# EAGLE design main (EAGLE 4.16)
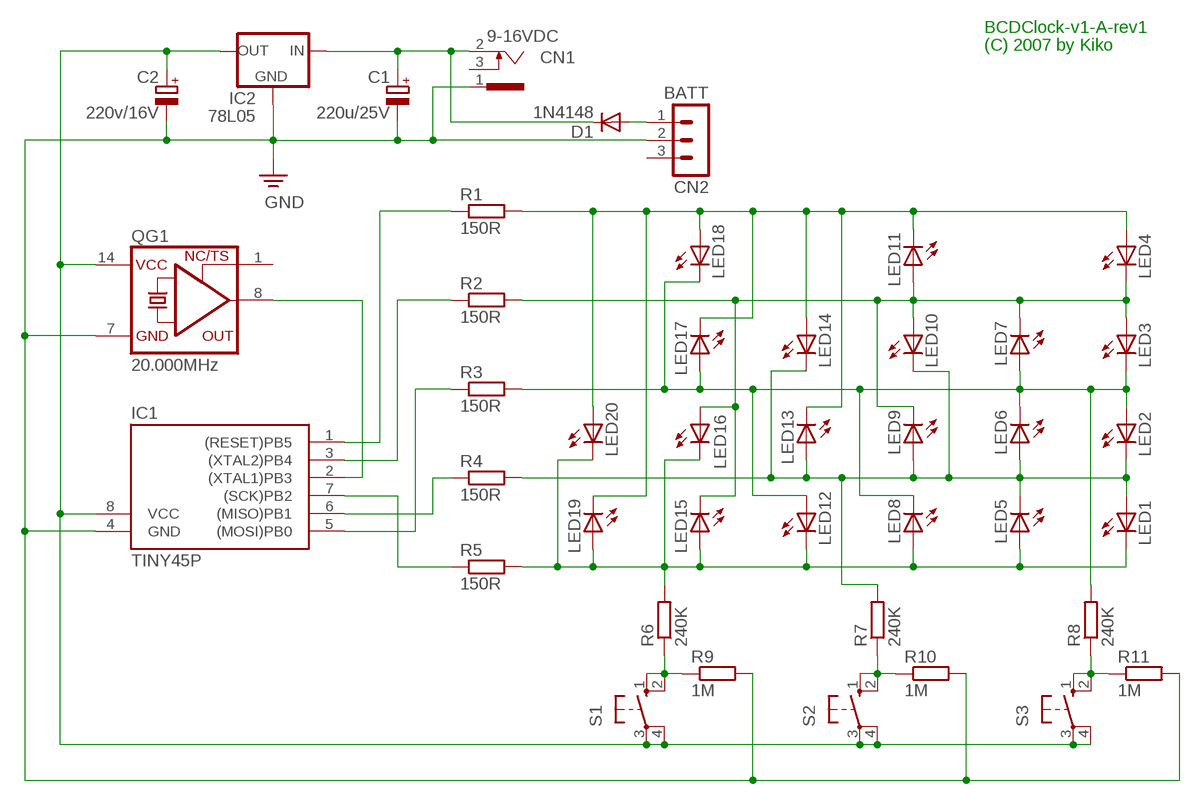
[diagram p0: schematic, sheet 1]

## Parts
C1  220u/25V  CPOL-EUE2.5-6  [E2,5-6]
C2  220v/16V  CPOL-EUE2.5-5  [E2,5-5]
CN1  9-16VDC  SCD-014A  [SCD-014-A]
CN2  BATT  MA03-1  [MA03-1]
D1  1N4148  [DO35-10]
IC1  TINY45P  TINY12P  [DIL08]
IC2  78L05  78LXX  [78LXX]
LED1  LED5MM  [LED5MM]
LED2  LED5MM  [LED5MM]
LED3  LED5MM  [LED5MM]
LED4  LED5MM  [LED5MM]
LED5  LED5MM  [LED5MM]
LED6  LED5MM  [LED5MM]
LED7  LED5MM  [LED5MM]
LED8  LED5MM  [LED5MM]
LED9  LED5MM  [LED5MM]
LED10  LED5MM  [LED5MM]
LED11  LED5MM  [LED5MM]
LED12  LED5MM  [LED5MM]
LED13  LED5MM  [LED5MM]
LED14  LED5MM  [LED5MM]
LED15  LED5MM  [LED5MM]
LED16  LED5MM  [LED5MM]
LED17  LED5MM  [LED5MM]
LED18  LED5MM  [LED5MM]
LED19  LED5MM  [LED5MM]
LED20  LED5MM  [LED5MM]
QG1  20.000MHz  XO-14  [DIL14S]
R1  150R  R-EU_0207/7  [0207/7]
R2  150R  R-EU_0207/7  [0207/7]
R3  150R  R-EU_0207/7  [0207/7]
R4  150R  R-EU_0207/7  [0207/7]
R5  150R  R-EU_0207/7  [0207/7]
R6  240K  R-EU_0207/7  [0207/7]
R7  240K  R-EU_0207/7  [0207/7]
R8  240K  R-EU_0207/7  [0207/7]
R9  1M  R-EU_0207/7  [0207/7]
R10  1M  R-EU_0207/7  [0207/7]
R11  1M  R-EU_0207/7  [0207/7]
S1  40-XX  [B3F-40XX]
S2  40-XX  [B3F-40XX]
S3  40-XX  [B3F-40XX]

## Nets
GND: C1.- C2.- CN1.1 CN2.2 IC1.4(GND) IC2.GND QG1.7(GND) R9.2 R10.2 R11.2
N$1: C1.+ CN1.2 D1.C IC2.IN
N$2: C2.+ IC1.8(VCC) IC2.OUT QG1.14(VCC) S1.3(P) S1.4(P1) S2.3(P) S2.4(P1) S3.3(P) S3.4(P1)
N$3: IC1.2((XTAL1)PB3) QG1.8(OUT)
N$4: IC1.1((RESET)PB5) R1.1
N$5: IC1.3((XTAL2)PB4) R2.1
N$6: IC1.5((MOSI)PB0) R3.1
N$7: IC1.6((MISO)PB1) R4.1
N$8: IC1.7((SCK)PB2) R5.1
N$9: LED4.A LED11.K(C) LED13.K(C) LED14.A LED17.K(C) LED18.A LED19.K(C) LED20.A R1.2
N$10: LED3.A LED4.K(C) LED7.K(C) LED9.K(C) LED10.A LED11.A LED15.K(C) LED16.A R2.2
N$11: LED1.K(C) LED5.A LED8.A LED12.K(C) LED15.A LED16.K(C) LED19.A LED20.K(C) R5.2 R6.2
N$12: LED1.A LED2.K(C) LED5.K(C) LED6.A LED9.A LED10.K(C) LED13.A LED14.K(C) R4.2 R7.2
N$13: LED2.A LED3.K(C) LED6.K(C) LED7.A LED8.K(C) LED12.A LED17.A LED18.K(C) R3.2 R8.2
N$14: CN2.1 D1.A
N$15: R6.1 R9.1 S1.1(S) S1.2(S1)
N$16: R7.1 R10.1 S2.1(S) S2.2(S1)
N$17: R8.1 R11.1 S3.1(S) S3.2(S1)
Unconnected: CN1.3 CN2.3 QG1.1(TS)

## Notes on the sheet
- BCDClock-v1-A-rev1
- (C) 2007 by Kiko

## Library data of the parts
C1 C2 = rcl:CPOL-EU: POLARIZED CAPACITOR, European symbol
CN1 = con-shiua-chyuan:SCD-014A: Power Jack 2.5mm
CN2 = con-lstb:MA03-1: PIN HEADER
D1 = diode:1N4148: DIODE
IC1 = atmel2:TINY12*: MICROCONTROLLER 1 Kbytes FLASH 64 bytes EEPROM
IC2 = v-reg:78LXX: VOLTAGE REGULATOR
LED1-LED20 = led:LED: LED
QG1 = crystal:XO-: CRYSTAL
R1-R11 = rcl:R-EU_: RESISTOR, European symbol
S1-S3 = switch-omron:40-XX: OMRON SWITCH

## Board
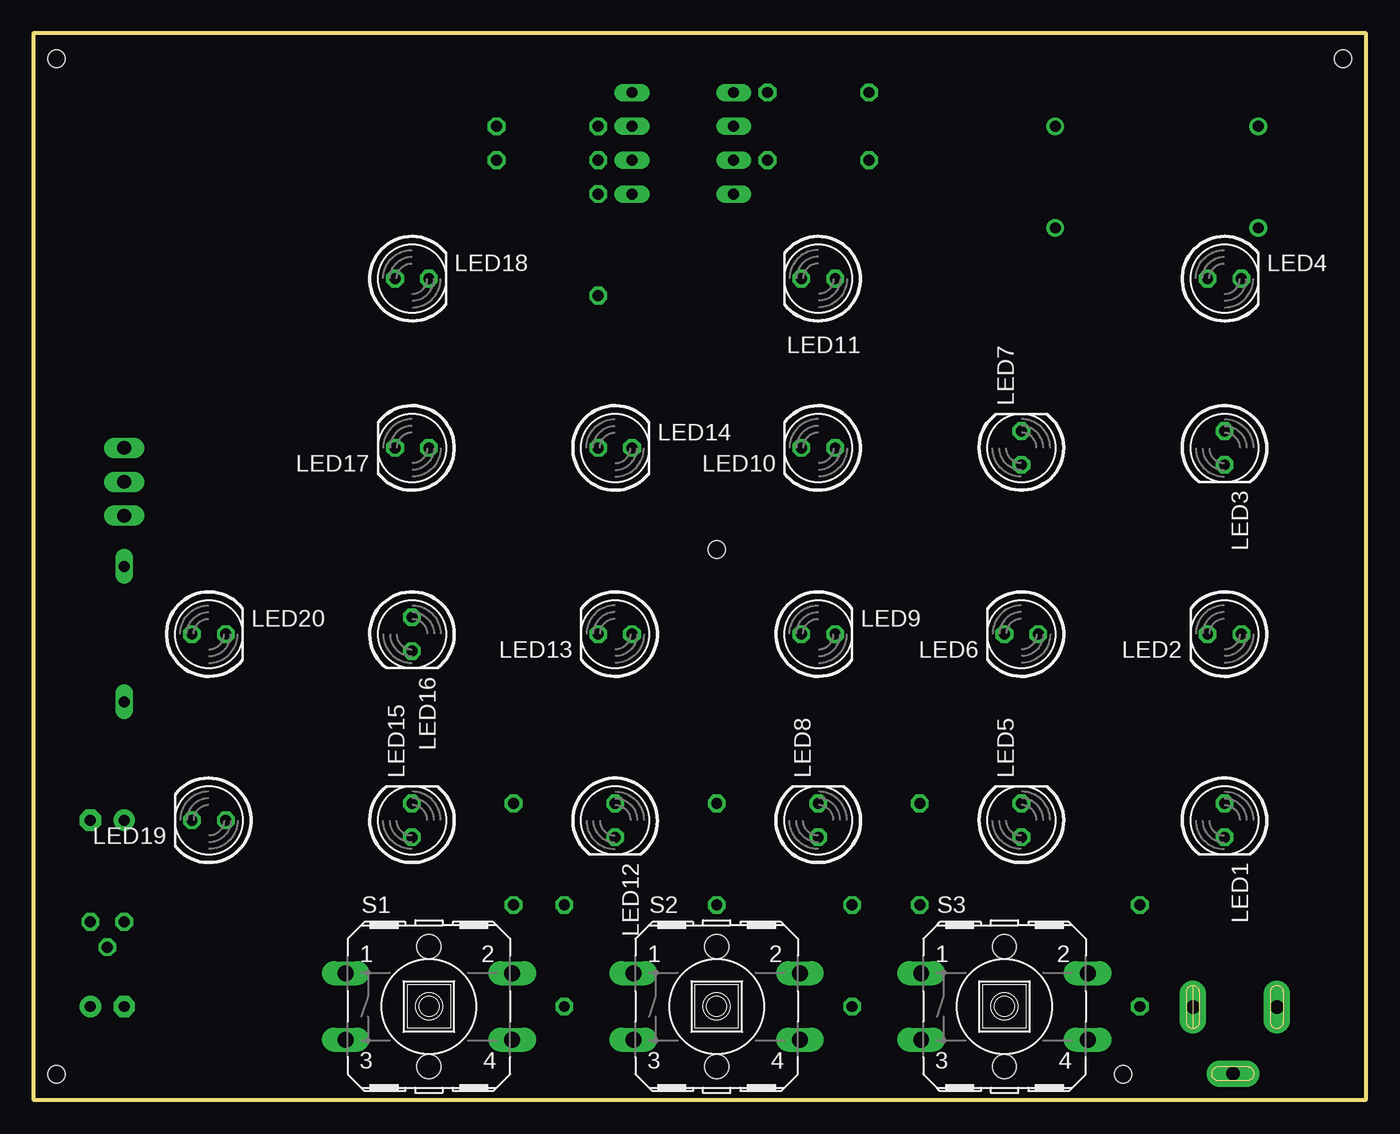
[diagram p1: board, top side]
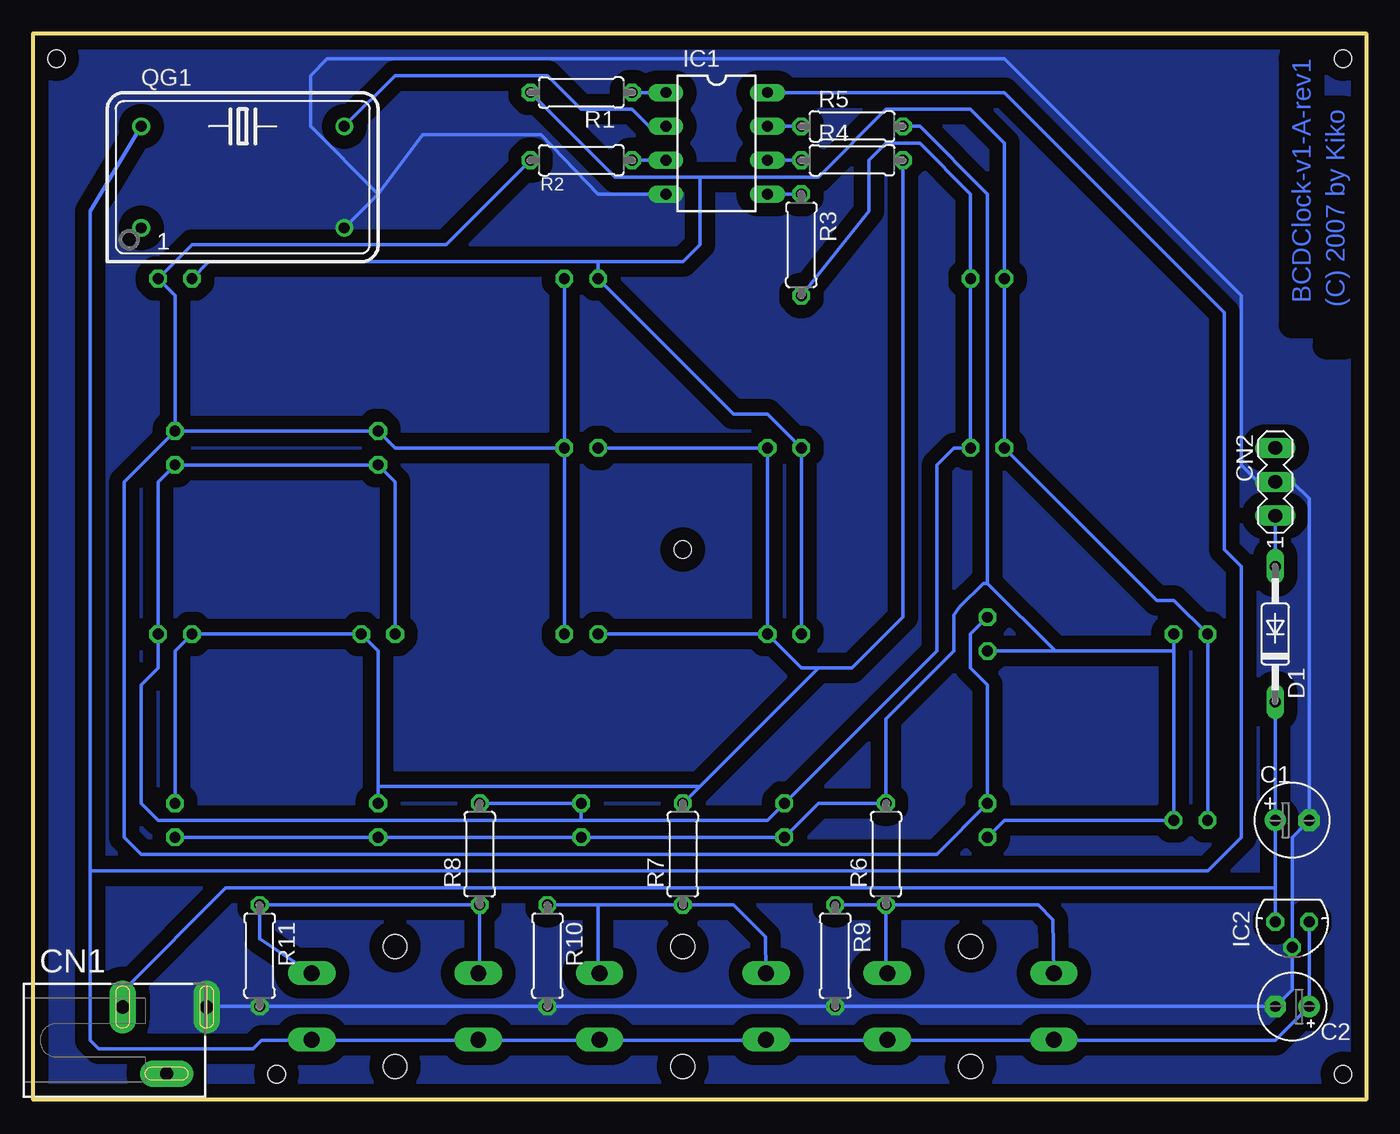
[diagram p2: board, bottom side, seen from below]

Size 100 x 80 mm. Coordinates in mm from the lower left corner, seen from the top.
Outline: 0,0 100,0 100,80 0,80 0,0
Copper layers (1*16): Top 0.035mm / dielectric 1.5mm / Bottom 0.035mm
Design rules "default": minimum track width 10mil, minimum drill 24mil, track to track 8mil, track to pad 8mil, pad to pad 8mil, via to via 8mil, smd to smd 8mil, copper to edge 40mil, drill to drill 8mil, minimum pad ring 10mil, minimum via ring 8mil, stop-mask expansion 4mil, vias tented up to drill 0mil, thermal gap 10mil
Holes 1.3 mm at 1.74,1.9 1.74,78.1 98.26,78.1 81.75,1.9 51.27,41.27

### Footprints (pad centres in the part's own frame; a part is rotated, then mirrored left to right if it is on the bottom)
E2,5-6 = drill 0.813 pad 1.6 round: + -1.27,0 | drill 0.813 pad 1.6 octagon: - 1.27,0
E2,5-5 = drill 0.813 pad 1.6 round: + -1.27,0 | drill 0.813 pad 1.6 octagon: - 1.27,0
SCD-014-A = drill 1 pad 2 long: 1 -2.5,13.8; 2 -2.5,7.5; 3 2.5,10.8
MA03-1 = drill 1.016 long: 1 -2.54,0; 2 0,0; 3 2.54,0
DO35-10 = drill 0.813 long: A 5.08,0; C -5.08,0
DIL08 = drill 0.813 long: 1 -3.81,-3.81; 2 -1.27,-3.81; 3 1.27,-3.81; 4 3.81,-3.81; 5 3.81,3.81; 6 1.27,3.81; 7 -1.27,3.81; 8 -3.81,3.81
78LXX = drill 0.813 octagon: GND 0,1.905; IN 1.27,0; OUT -1.27,0
LED5MM = drill 0.813 octagon: A -1.27,0; K 1.27,0
DIL14S = drill 0.813 round: 1 -7.62,-3.81; 7 7.62,-3.81; 8 7.62,3.81; 14 -7.62,3.81
0207/7 = drill 0.813 octagon: 1 -3.81,0; 2 3.81,0
B3F-40XX = drill 1.194 long: 1 -6.248,2.489; 2 6.248,2.489; 3 -6.248,-2.489; 4 6.248,-2.489 | hole 1.803: 0,-4.496; 0,4.496

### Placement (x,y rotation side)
C1  5.55,20.95 0 bottom
C2  5.55,6.98 180 bottom
CN1  100.8,4.44 270 bottom
CN2  6.82,46.35 90 bottom
D1  6.82,34.92 90 bottom
IC1  48.73,71.75 270 bottom
IC2  5.55,13.33 180 bottom
LED1  89.37,20.95 270 top
LED2  89.37,34.92 180 top
LED3  89.37,48.89 270 top
LED4  89.37,61.59 0 top
LED5  74.13,20.95 90 top
LED6  74.13,34.92 180 top
LED7  74.13,48.89 90 top
LED8  58.89,20.95 90 top
LED9  58.89,34.92 0 top
LED10  58.89,48.89 180 top
LED11  58.89,61.59 180 top
LED12  43.65,20.95 270 top
LED13  43.65,34.92 180 top
LED14  43.65,48.89 0 top
LED15  28.41,20.95 90 top
LED16  28.41,34.92 270 top
LED17  28.41,48.89 180 top
LED18  28.41,61.59 0 top
LED19  13.17,20.95 180 top
LED20  13.17,34.92 0 top
QG1  84.29,69.21 0 bottom
R1  58.89,75.56 180 bottom
R2  58.89,70.48 180 bottom
R3  42.38,64.13 270 bottom
R4  38.57,70.48 0 bottom
R5  38.57,73.02 0 bottom
R6  36.03,18.41 90 bottom
R7  51.27,18.41 90 bottom
R8  66.51,18.41 90 bottom
R9  39.84,10.79 270 bottom
R10  61.43,10.79 270 bottom
R11  83.02,10.79 270 bottom
S1  29.68,6.98 0 top
S2  51.27,6.98 0 top
S3  72.86,6.98 0 top

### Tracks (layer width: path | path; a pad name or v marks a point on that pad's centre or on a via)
GND
  Bottom 0.254: CN1.1 86.83,6.98 R11.2 R10.2 R9.2 C2.- 5.55,8.25 IC2.GND 5.55,19.68 C1.- 4.28,45.08 5.55,46.35 CN2.2 8.09,46.35 9.36,47.62 9.36,60.32 27.14,78.1 77.94,78.1 79.21,76.83 79.21,73.02 74.13,67.94 | 74.13,67.94 QG1.7 | 74.13,67.94 70.8,72.38 61.91,72.38 57.62,67.94 IC1.4
  pour Bottom (isolate 1.016, no thermals): 0.47,79.37 0.47,0.63 99.53,0.63 99.53,79.37
N$1
  Bottom 0.254: 6.82,15.87 C1.+ D1.C | IC2.IN 6.82,15.87 | 6.82,15.87 85.56,15.87 93.18,8.25 CN1.2
N$2
  Bottom 0.254: IC2.OUT C2.+ 6.82,4.44 22.06,4.44 S1.3 24.6,4.44 33.49,4.44 | 33.49,4.44 34.76,4.44 S1.4 37.3,4.44 43.65,4.44 S2.3 | 33.49,4.44 56.35,4.44 S2.4 58.89,4.44 65.24,4.44 S3.3 67.78,4.44 77.94,4.44 S3.4 80.48,4.44 82.86,4.44 83.5,3.8 95.08,3.8 95.72,4.44 95.72,17.14 | QG1.14 95.72,66.67 95.72,17.14 | 95.72,17.14 11.9,17.14 9.36,19.68 9.36,40 10.63,41.27 10.63,59.05 27.14,75.56 IC1.8
N$3
  Bottom 0.254: QG1.8 72.86,76.83 61.43,76.83 58.89,74.29 55.08,74.29 53.81,73.02 IC1.2
N$4
  Bottom 0.254: IC1.1 R1.1
N$5
  Bottom 0.254: IC1.3 R2.1
N$6
  Bottom 0.254: R3.1 IC1.5
N$7
  Bottom 0.254: R4.1 IC1.6
N$8
  Bottom 0.254: R5.1 IC1.7
N$9
  Bottom 0.254: LED19.K LED20.A 14.44,37.46 15.71,37.46 LED17.K LED18.A 27.14,71.75 29.68,74.29 36.03,74.29 41.11,69.21 50,69.21 | LED13.K LED14.A 44.92,51.43 47.46,51.43 LED11.K 57.62,62.86 | R1.2 56.35,69.21 50,69.21 | 50,69.21 50,64.13 51.27,62.86 57.62,62.86 | LED4.A 86.83,62.86 57.62,62.86
N$10
  Bottom 0.254: LED10.A LED9.K | LED10.A 72.86,48.89 LED7.K LED3.A | LED10.A LED11.A | LED16.A 29.68,34.92 29.68,32.38 28.41,31.11 LED15.K 32.22,18.41 91.91,18.41 93.18,19.68 93.18,46.35 LED3.A | LED3.A 89.37,60.32 LED4.K 88.1,64.13 69.05,64.13 R2.2
N$11
  Bottom 0.254: LED1.K LED5.A LED8.A LED12.K 41.11,22.22 R6.2 36.03,28.57 30.95,33.65 30.95,36.35 30.47,36.98 28.73,38.73 28.41,38.73 | 14.44,33.65 LED20.K | 14.44,33.65 LED19.A 27.14,20.95 LED15.A | 14.44,33.65 23.33,33.65 | 23.33,33.65 LED16.K | R5.2 33.49,73.02 28.41,67.94 28.41,38.73 | 23.33,33.65 28.41,38.73
N$12
  Bottom 0.254: 74.13,23.49 74.13,33.65 LED6.A LED2.K 89.37,33.65 LED1.A | 74.13,23.49 LED5.K | LED10.K LED14.K LED13.A | R4.2 34.76,36.19 38.57,32.38 41.11,32.38 | 41.11,32.38 42.38,32.38 LED13.A | 41.11,32.38 50,23.49 | 50,23.49 R7.2 | LED13.A LED9.A | 50,23.49 74.13,23.49
N$13
  Bottom 0.254: LED6.K 72.86,46.35 LED7.A LED3.K 90.64,46.35 LED2.A 90.64,32.38 91.91,31.11 91.91,22.22 90.64,20.95 58.89,20.95 | 58.89,20.95 44.92,20.95 LED12.A 32.22,33.65 32.22,47.62 30.95,48.89 LED17.A LED18.K 29.68,67.94 33.49,71.75 36.03,71.75 37.3,70.48 37.3,66.67 R3.2 | 58.89,20.95 LED8.K R8.2
N$14
  Bottom 0.254: D1.A CN2.1
N$15
  Bottom 0.254: R6.1 R9.1 | R6.1 24.6,14.6 23.49,13.49 S1.1 | R6.1 36.03,9.52 S1.2
N$16
  Bottom 0.254: 57.62,14.6 R10.1 | 57.62,14.6 R7.1 47.46,14.6 45.08,12.22 S2.1 | 57.62,14.6 57.62,9.52 S2.2
N$17
  Bottom 0.254: S3.1 66.51,9.52 R8.1 R11.1 83.02,12.06 S3.2

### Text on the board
Bottom: BCDClock-v1-A-rev1 | (C) 2007 by Kiko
